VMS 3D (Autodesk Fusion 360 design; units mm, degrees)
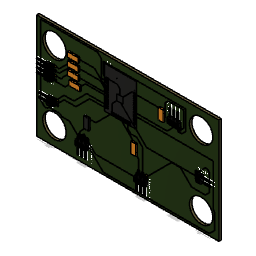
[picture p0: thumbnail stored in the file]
sketch "Outline" plane through (0, 0, 0) normal (0, 0, 1) x axis (1, 0, 0)
  line L1 (118, 0) -> (0, 0)
  line L2 (118, 68) -> (118, 0)
  line L3 (0, 68) -> (118, 68)
  line L4 (0, 0) -> (0, 68)
canvas "Canvas1" bodies "Board"
canvas "Canvas2" bodies "Board"
pcbhole "PCBHole1" HoleDepth 1.605 HoleDiameter 15.142 TipAngle 10313.2
pcbhole "PCBHole2" HoleDepth 1.605 HoleDiameter 15.142 TipAngle 10313.2
pcbhole "PCBHole3" HoleDepth 1.605 HoleDiameter 15.142 TipAngle 10313.2
pcbhole "PCBHole4" HoleDepth 1.605 HoleDiameter 15.142 TipAngle 10313.2
pcbhole "PCBHole5" HoleDepth 1.605 HoleDiameter 0.35 TipAngle 10313.2
pcbhole "PCBHole6" HoleDepth 1.605 HoleDiameter 0.35 TipAngle 10313.2
pcbhole "PCBHole7" HoleDepth 1.605 HoleDiameter 0.35 TipAngle 10313.2
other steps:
base_feature "Base Feature1"
base_feature "Base Feature1"
box_primitive "BoxPrimitive1" DistanceX 7.0612 DistanceY 3.2004 DistanceZ 1 OffsetDistanceX 0 OffsetDistanceY 0
pcbextrude "PCBExtrude1"
pcbextrude "PCBExtrude1"
base_feature "Base Feature1"
box_primitive "BoxPrimitive1" DistanceX 20.69 DistanceY 26.905 DistanceZ 0.1 OffsetDistanceX 0 OffsetDistanceY 0
extrude "Extrude1" sketch "Outline" blind 1.5 bodies "Board"
pcbextrude "PCBExtrude1"
pcbextrude "PCBExtrude1"
pcbhole "PCBHole1" HoleDepth 1.606 HoleDiameter 15.142 TipAngle 10313.2
pcbhole "PCBHole1" HoleDepth 1.606 HoleDiameter 15.142 TipAngle 10313.2
pcbhole "PCBHole2" HoleDepth 1.606 HoleDiameter 15.142 TipAngle 10313.2
pcbhole "PCBHole2" HoleDepth 1.606 HoleDiameter 15.142 TipAngle 10313.2
pcbhole "PCBHole3" HoleDepth 1.606 HoleDiameter 15.142 TipAngle 10313.2
pcbhole "PCBHole3" HoleDepth 1.606 HoleDiameter 15.142 TipAngle 10313.2
pcbhole "PCBHole4" HoleDepth 1.606 HoleDiameter 15.142 TipAngle 10313.2
pcbhole "PCBHole4" HoleDepth 1.606 HoleDiameter 15.142 TipAngle 10313.2
pcbhole "PCBHole5" HoleDepth 1.606 HoleDiameter 0.35 TipAngle 10313.2
pcbhole "PCBHole5" HoleDepth 1.606 HoleDiameter 0.35 TipAngle 10313.2
pcbhole "PCBHole6" HoleDepth 1.606 HoleDiameter 0.35 TipAngle 10313.2
pcbhole "PCBHole6" HoleDepth 1.606 HoleDiameter 0.35 TipAngle 10313.2
pcbhole "PCBHole7" HoleDepth 1.606 HoleDiameter 0.35 TipAngle 10313.2
pcbhole "PCBHole7" HoleDepth 1.606 HoleDiameter 0.35 TipAngle 10313.2
pcbextrude "PCBExtrude1"
pcbextrude "PCBExtrude2" bodies "CopperHoles"
create_component "CreateComponent1"
create_component "CreateComponent2"
create_component "CreateComponent3"
create_component "CreateComponent4"
create_component "CreateComponent5"
create_component "CreateComponent6"
as_built_joint "As-built1"
create_component "CreateComponent3"
create_component "CreateComponent4"
create_component "CreateComponent9"
create_component "CreateComponent10"
create_component "CreateComponent11"
named bodies: "Board", "CopperHoles"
